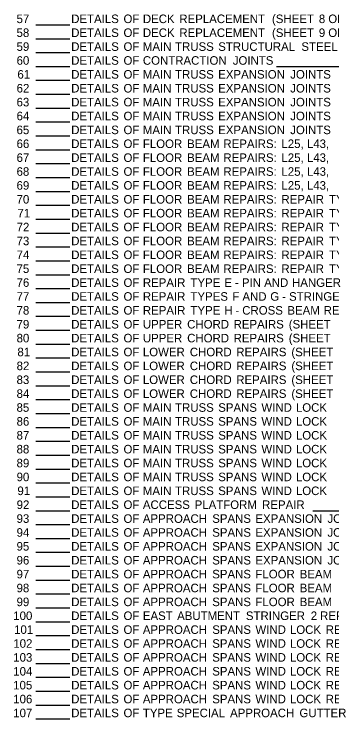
# Model space of a CAD drawing. Extents: x 76 to 3247, y 35 to 1167.
# Drawn here: x 158 to 381.2, y 87.2 to 582.2 of the extents above; entities that cross this region are included whole.
import ezdxf

# ---------------------------------------------------------------- set-up
doc = ezdxf.new("R2010")
doc.units = 0
doc.layers.add('Default', color=7, linetype='Continuous')

msp = doc.modelspace()

# ---------------------------------------------------------------- linework, layer by layer
at = {"layer": 'Default'}
for p, q in [((173.25, 574.65), (197.14, 574.65)), ((173.25, 564.9), (197.14, 564.9)), ((173.25, 555.15), (197.14, 555.15)), ((173.25, 545.4), (197.14, 545.4)), ((342.31, 545.4), (711.45, 545.4)), ((173.25, 535.65), (197.14, 535.65)), ((173.25, 525.9), (197.14, 525.9)), ((173.25, 516.15), (197.14, 516.15)), ((173.25, 506.4), (197.14, 506.4)), ((173.25, 496.65), (197.14, 496.65)), ((173.25, 486.9), (197.14, 486.9)), ((173.25, 477.15), (197.14, 477.15)), ((173.25, 467.4), (197.14, 467.4)), ((173.25, 457.65), (197.14, 457.65)), ((173.25, 447.9), (197.14, 447.9)), ((173.25, 438.15), (197.14, 438.15)), ((173.25, 428.4), (197.14, 428.4)), ((173.25, 418.65), (197.14, 418.65)), ((173.25, 408.9), (197.14, 408.9)), ((173.25, 399.15), (197.14, 399.15)), ((173.25, 389.4), (197.14, 389.4)), ((173.25, 379.65), (197.14, 379.65)), ((173.25, 369.9), (197.14, 369.9)), ((173.25, 360.15), (197.14, 360.15)), ((173.25, 350.4), (197.14, 350.4)), ((173.25, 340.65), (197.14, 340.65)), ((173.25, 330.9), (197.14, 330.9)), ((173.25, 321.15), (197.14, 321.15)), ((173.25, 311.4), (197.14, 311.4)), ((173.25, 301.65), (197.14, 301.65)), ((173.25, 291.9), (197.14, 291.9)), ((173.25, 282.15), (197.14, 282.15)), ((173.25, 272.4), (197.14, 272.4)), ((173.25, 262.65), (197.14, 262.65)), ((173.25, 252.9), (197.14, 252.9)), ((173.25, 243.15), (197.14, 243.15)), ((173.25, 233.4), (197.14, 233.4)), ((367.88, 233.4), (711.45, 233.4)), ((173.25, 223.65), (197.14, 223.65)), ((173.25, 213.9), (197.14, 213.9)), ((173.25, 204.15), (197.14, 204.15)), ((173.25, 194.4), (197.14, 194.4)), ((173.25, 184.65), (197.14, 184.65)), ((173.25, 174.9), (197.14, 174.9)), ((173.25, 165.15), (197.14, 165.15)), ((173.25, 155.4), (197.14, 155.4)), ((173.25, 145.65), (197.14, 145.65)), ((173.25, 135.9), (197.14, 135.9)), ((173.25, 126.15), (197.14, 126.15)), ((173.25, 116.4), (197.14, 116.4)), ((173.25, 106.65), (197.14, 106.65)), ((173.25, 96.9), (197.14, 96.9)), ((173.25, 87.15), (197.14, 87.15))]:
    msp.add_line(p, q, dxfattribs=at)

# ---------------------------------------------------------------- texts
for s, p in [('57', (159.76, 575.85)), ('DETAILS', (198.11, 575.85)), (' OF', (232.61, 575.85)), (' DECK', (246.2, 575.85)), (' REPLACEMENT', (271.81, 575.85)), (' (SHEET', (336.86, 575.85)), (' 8', (369.76, 575.85)), (' OF', (376.38, 575.85)), ('58', (159.75, 566.1)), ('DETAILS', (198.11, 566.1)), (' OF', (232.61, 566.1)), (' DECK', (246.2, 566.1)), (' REPLACEMENT', (271.81, 566.1)), (' (SHEET', (336.86, 566.1)), (' 9', (369.76, 566.1)), (' OF', (376.38, 566.1)), ('59', (159.75, 556.35)), ('DETAILS', (198.11, 556.35)), (' OF', (232.61, 556.35)), (' MAIN', (246.2, 556.35)), (' TRUSS', (268.8, 556.35)), (' STRUCTURAL', (299.11, 556.35)), (' STEEL', (357.5, 556.35)), ('60', (159.77, 546.6)), ('DETAILS', (198.11, 546.6)), (' OF', (232.61, 546.6)), (' CONTRACTION', (246.2, 546.6)), (' JOINTS', (309.33, 546.6)), ('61', (160.34, 536.85)), ('DETAILS', (198.11, 536.85)), (' OF', (232.61, 536.85)), (' MAIN', (246.2, 536.85)), (' TRUSS', (268.8, 536.85)), (' EXPANSION', (299.11, 536.85)), (' JOINTS', (349.67, 536.85)), ('62', (159.79, 527.1)), ('DETAILS', (198.11, 527.1)), (' OF', (232.61, 527.1)), (' MAIN', (246.2, 527.1)), (' TRUSS', (268.8, 527.1)), (' EXPANSION', (299.11, 527.1)), (' JOINTS', (349.67, 527.1)), ('63', (159.76, 517.35)), ('DETAILS', (198.11, 517.35)), (' OF', (232.61, 517.35)), (' MAIN', (246.2, 517.35)), (' TRUSS', (268.8, 517.35)), (' EXPANSION', (299.11, 517.35)), (' JOINTS', (349.67, 517.35)), ('64', (159.77, 507.6)), ('DETAILS', (198.11, 507.6)), (' OF', (232.61, 507.6)), (' MAIN', (246.2, 507.6)), (' TRUSS', (268.8, 507.6)), (' EXPANSION', (299.11, 507.6)), (' JOINTS', (349.67, 507.6)), ('65', (159.74, 497.85)), ('DETAILS', (198.11, 497.85)), (' OF', (232.61, 497.85)), (' MAIN', (246.2, 497.85)), (' TRUSS', (268.8, 497.85)), (' EXPANSION', (299.11, 497.85)), (' JOINTS', (349.67, 497.85)), ('66', (159.76, 488.1)), ('DETAILS', (198.11, 488.1)), (' OF', (232.61, 488.1)), (' FLOOR', (246.2, 488.1)), (' BEAM', (277.29, 488.1)), (' REPAIRS:', (302.75, 488.1)), (' L25,', (343.49, 488.1)), (' L43,', (361.38, 488.1)), ('67', (159.76, 478.35)), ('DETAILS', (198.11, 478.35)), (' OF', (232.61, 478.35)), (' FLOOR', (246.2, 478.35)), (' BEAM', (277.29, 478.35)), (' REPAIRS:', (302.75, 478.35)), (' L25,', (343.49, 478.35)), (' L43,', (361.38, 478.35)), ('68', (159.75, 468.6)), ('DETAILS', (198.11, 468.6)), (' OF', (232.61, 468.6)), (' FLOOR', (246.2, 468.6)), (' BEAM', (277.29, 468.6)), (' REPAIRS:', (302.75, 468.6)), (' L25,', (343.49, 468.6)), (' L43,', (361.38, 468.6)), ('69', (159.75, 458.85)), ('DETAILS', (198.11, 458.85)), (' OF', (232.61, 458.85)), (' FLOOR', (246.2, 458.85)), (' BEAM', (277.29, 458.85)), (' REPAIRS:', (302.75, 458.85)), (' L25,', (343.49, 458.85)), (' L43,', (361.38, 458.85)), ('70', (159.77, 449.1)), ('DETAILS', (198.11, 449.1)), (' OF', (232.61, 449.1)), (' FLOOR', (246.2, 449.1)), (' BEAM', (277.29, 449.1)), (' REPAIRS:', (302.75, 449.1)), (' REPAIR', (343.49, 449.1)), (' TYPE', (376.92, 449.1)), ('71', (160.34, 439.35)), ('DETAILS', (198.11, 439.35)), (' OF', (232.61, 439.35)), (' FLOOR', (246.2, 439.35)), (' BEAM', (277.29, 439.35)), (' REPAIRS:', (302.75, 439.35)), (' REPAIR', (343.49, 439.35)), (' TYPE', (376.92, 439.35)), ('72', (159.79, 429.6)), ('DETAILS', (198.11, 429.6)), (' OF', (232.61, 429.6)), (' FLOOR', (246.2, 429.6)), (' REPAIRS:', (302.75, 429.6)), (' BEAM', (277.29, 429.6)), (' REPAIR', (343.49, 429.6)), (' TYPE', (376.92, 429.6)), ('73', (159.76, 419.85)), ('DETAILS', (198.11, 419.85)), (' OF', (232.61, 419.85)), (' FLOOR', (246.2, 419.85)), (' BEAM', (277.29, 419.85)), (' REPAIRS:', (302.75, 419.85)), (' REPAIR', (343.49, 419.85)), (' TYPE', (376.92, 419.85)), ('74', (159.77, 410.1)), ('DETAILS', (198.11, 410.1)), (' OF', (232.61, 410.1)), (' FLOOR', (246.2, 410.1)), (' BEAM', (277.29, 410.1)), (' REPAIRS:', (302.75, 410.1)), (' REPAIR', (343.49, 410.1)), (' TYPE', (376.92, 410.1)), ('75', (159.74, 400.35)), ('DETAILS', (198.11, 400.35)), (' OF', (232.61, 400.35)), (' FLOOR', (246.2, 400.35)), (' BEAM', (277.29, 400.35)), (' REPAIRS:', (302.75, 400.35)), (' REPAIR', (343.49, 400.35)), (' TYPE', (376.92, 400.35)), ('76', (159.76, 390.6)), ('DETAILS', (198.11, 390.6)), (' OF', (232.61, 390.6)), (' REPAIR', (246.2, 390.6)), (' TYPE', (279.63, 390.6)), (' E', (303.41, 390.6)), (' PIN', (315.74, 390.6)), (' AND', (331.36, 390.6)), (' HANGER', (350.94, 390.6)), (' -', (310.88, 390.6)), ('77', (159.76, 380.85)), ('DETAILS', (198.11, 380.85)), (' OF', (232.61, 380.85)), (' REPAIR', (246.2, 380.85)), (' TYPES', (279.63, 380.85)), (' F', (309.01, 380.85)), (' AND', (316.08, 380.85)), (' G', (335.66, 380.85)), (' STRINGER', (348.84, 380.85)), (' -', (343.99, 380.85)), ('78', (159.75, 371.1)), ('DETAILS', (198.11, 371.1)), (' OF', (232.61, 371.1)), (' REPAIR', (246.2, 371.1)), (' TYPE', (279.63, 371.1)), (' H', (303.41, 371.1)), (' CROSS', (315.97, 371.1)), (' BEAM', (347.68, 371.1)), (' REPLACEMENT', (373.14, 371.1)), (' -', (311.12, 371.1)), ('79', (159.75, 361.35)), ('DETAILS', (198.11, 361.35)), (' OF', (232.61, 361.35)), (' UPPER', (246.2, 361.35)), (' CHORD', (277.3, 361.35)), (' REPAIRS', (309.92, 361.35)), (' (SHEET', (348.62, 361.35)), ('80', (159.77, 351.6)), ('DETAILS', (198.11, 351.6)), (' OF', (232.61, 351.6)), (' UPPER', (246.2, 351.6)), (' CHORD', (277.3, 351.6)), (' REPAIRS', (309.92, 351.6)), (' (SHEET', (348.62, 351.6)), ('81', (160.34, 341.85)), ('DETAILS', (198.11, 341.85)), (' OF', (232.61, 341.85)), (' LOWER', (246.2, 341.85)), (' CHORD', (279.16, 341.85)), (' REPAIRS', (311.78, 341.85)), (' (SHEET', (350.47, 341.85)), ('82', (159.79, 332.1)), ('DETAILS', (198.11, 332.1)), (' OF', (232.61, 332.1)), (' LOWER', (246.2, 332.1)), (' CHORD', (279.16, 332.1)), (' REPAIRS', (311.78, 332.1)), (' (SHEET', (350.47, 332.1)), ('83', (159.76, 322.35)), ('DETAILS', (198.11, 322.35)), (' OF', (232.61, 322.35)), (' LOWER', (246.2, 322.35)), (' CHORD', (279.16, 322.35)), (' REPAIRS', (311.78, 322.35)), (' (SHEET', (350.47, 322.35)), ('84', (159.77, 312.6)), ('DETAILS', (198.11, 312.6)), (' OF', (232.61, 312.6)), (' LOWER', (246.2, 312.6)), (' CHORD', (279.16, 312.6)), (' REPAIRS', (311.78, 312.6)), (' (SHEET', (350.47, 312.6)), ('85', (159.74, 302.85)), ('DETAILS', (198.11, 302.85)), (' OF', (232.61, 302.85)), (' MAIN', (246.2, 302.85)), (' TRUSS', (268.8, 302.85)), (' SPANS', (299.11, 302.85)), (' WIND', (329.42, 302.85)), (' LOCK', (353.65, 302.85)), ('86', (159.76, 293.1)), ('DETAILS', (198.11, 293.1)), (' OF', (232.61, 293.1)), (' MAIN', (246.2, 293.1)), (' TRUSS', (268.8, 293.1)), (' SPANS', (299.11, 293.1)), (' WIND', (329.42, 293.1)), (' LOCK', (353.65, 293.1)), ('87', (159.76, 283.35)), ('DETAILS', (198.11, 283.35)), (' OF', (232.61, 283.35)), (' MAIN', (246.2, 283.35)), (' TRUSS', (268.8, 283.35)), (' SPANS', (299.11, 283.35)), (' WIND', (329.42, 283.35)), (' LOCK', (353.65, 283.35)), ('88', (159.75, 273.6)), ('DETAILS', (198.11, 273.6)), (' OF', (232.61, 273.6)), (' MAIN', (246.2, 273.6)), (' TRUSS', (268.8, 273.6)), (' SPANS', (299.11, 273.6)), (' WIND', (329.42, 273.6)), (' LOCK', (353.65, 273.6)), ('89', (159.75, 263.85)), ('DETAILS', (198.11, 263.85)), (' OF', (232.61, 263.85)), (' MAIN', (246.2, 263.85)), (' TRUSS', (268.8, 263.85)), (' SPANS', (299.11, 263.85)), (' WIND', (329.42, 263.85)), (' LOCK', (353.65, 263.85)), ('90', (159.77, 254.1)), ('DETAILS', (198.11, 254.1)), (' OF', (232.61, 254.1)), (' MAIN', (246.2, 254.1)), (' TRUSS', (268.8, 254.1)), (' SPANS', (299.11, 254.1)), (' WIND', (329.42, 254.1)), (' LOCK', (353.65, 254.1)), ('91', (160.34, 244.35)), ('DETAILS', (198.11, 244.35)), (' OF', (232.61, 244.35)), (' MAIN', (246.2, 244.35)), (' TRUSS', (268.8, 244.35)), (' SPANS', (299.11, 244.35)), (' WIND', (329.42, 244.35)), (' LOCK', (353.65, 244.35)), ('92', (159.79, 234.6)), ('DETAILS', (198.11, 234.6)), (' OF', (232.61, 234.6)), (' ACCESS', (246.2, 234.6)), (' PLATFORM', (282.57, 234.6)), (' REPAIR', (329.92, 234.6)), ('93', (159.76, 224.85)), ('DETAILS', (198.11, 224.85)), (' OF', (232.61, 224.85)), (' APPROACH', (246.2, 224.85)), (' SPANS', (294.91, 224.85)), (' EXPANSION', (325.23, 224.85)), (' JOINTS', (375.79, 224.85)), ('94', (159.77, 215.1)), ('DETAILS', (198.11, 215.1)), (' OF', (232.61, 215.1)), (' APPROACH', (246.2, 215.1)), (' SPANS', (294.91, 215.1)), (' EXPANSION', (325.23, 215.1)), (' JOINTS', (375.79, 215.1)), ('95', (159.74, 205.35)), ('DETAILS', (198.11, 205.35)), (' OF', (232.61, 205.35)), (' APPROACH', (246.2, 205.35)), (' SPANS', (294.91, 205.35)), (' EXPANSION', (325.23, 205.35)), (' JOINTS', (375.79, 205.35)), ('96', (159.76, 195.6)), ('DETAILS', (198.11, 195.6)), (' OF', (232.61, 195.6)), (' APPROACH', (246.2, 195.6)), (' SPANS', (294.91, 195.6)), (' EXPANSION', (325.23, 195.6)), (' JOINTS', (375.79, 195.6)), ('97', (159.76, 185.85)), ('DETAILS', (198.11, 185.85)), (' OF', (232.61, 185.85)), (' APPROACH', (246.2, 185.85)), (' SPANS', (294.91, 185.85)), (' FLOOR', (325.23, 185.85)), (' BEAM', (356.32, 185.85)), ('98', (159.75, 176.1)), ('DETAILS', (198.11, 176.1)), (' OF', (232.61, 176.1)), (' APPROACH', (246.2, 176.1)), (' SPANS', (294.91, 176.1)), (' FLOOR', (325.23, 176.1)), (' BEAM', (356.32, 176.1)), ('99', (159.75, 166.35)), ('DETAILS', (198.11, 166.35)), (' OF', (232.61, 166.35)), (' APPROACH', (246.2, 166.35)), (' SPANS', (294.91, 166.35)), (' FLOOR', (325.23, 166.35)), (' BEAM', (356.32, 166.35)), ('100', (157.44, 156.6)), ('DETAILS', (198.11, 156.6)), (' OF', (232.61, 156.6)), (' EAST', (246.2, 156.6)), (' ABUTMENT', (270.26, 156.6)), (' STRINGER', (318.54, 156.6)), (' 2', (364.07, 156.6)), (' REPAIR', (370.61, 156.6)), ('101', (158.01, 146.85)), ('DETAILS', (198.11, 146.85)), (' OF', (232.61, 146.85)), (' APPROACH', (246.2, 146.85)), (' SPANS', (294.91, 146.85)), (' WIND', (325.23, 146.85)), (' LOCK', (349.45, 146.85)), (' REPLACEMENT', (374.59, 146.85)), ('102', (157.46, 137.1)), ('DETAILS', (198.11, 137.1)), (' OF', (232.61, 137.1)), (' APPROACH', (246.2, 137.1)), (' SPANS', (294.91, 137.1)), (' WIND', (325.23, 137.1)), (' LOCK', (349.45, 137.1)), (' REPLACEMENT', (374.59, 137.1)), ('103', (157.43, 127.35)), ('DETAILS', (198.11, 127.35)), (' OF', (232.61, 127.35)), (' APPROACH', (246.2, 127.35)), (' SPANS', (294.91, 127.35)), (' WIND', (325.23, 127.35)), (' LOCK', (349.45, 127.35)), (' REPLACEMENT', (374.59, 127.35)), ('104', (157.44, 117.6)), ('DETAILS', (198.11, 117.6)), (' OF', (232.61, 117.6)), (' APPROACH', (246.2, 117.6)), (' SPANS', (294.91, 117.6)), (' WIND', (325.23, 117.6)), (' LOCK', (349.45, 117.6)), (' REPLACEMENT', (374.59, 117.6)), ('105', (157.41, 107.85)), ('DETAILS', (198.11, 107.85)), (' OF', (232.61, 107.85)), (' APPROACH', (246.2, 107.85)), (' SPANS', (294.91, 107.85)), (' LOCK', (349.45, 107.85)), (' REPLACEMENT', (374.59, 107.85)), (' WIND', (325.23, 107.85)), ('106', (157.43, 98.1)), ('DETAILS', (198.11, 98.1)), (' OF', (232.61, 98.1)), (' APPROACH', (246.2, 98.1)), (' SPANS', (294.91, 98.1)), (' WIND', (325.23, 98.1)), (' LOCK', (349.45, 98.1)), (' REPLACEMENT', (374.59, 98.1)), ('107', (157.43, 88.35)), ('DETAILS', (198.11, 88.35)), (' OF', (232.61, 88.35)), (' TYPE', (246.2, 88.35)), (' SPECIAL', (269.98, 88.35)), (' APPROACH', (307.43, 88.35)), (' GUTTER', (356.14, 88.35))]:
    msp.add_text(s, height=6, dxfattribs=at).set_placement(p)

doc.saveas('drawing.dxf')
